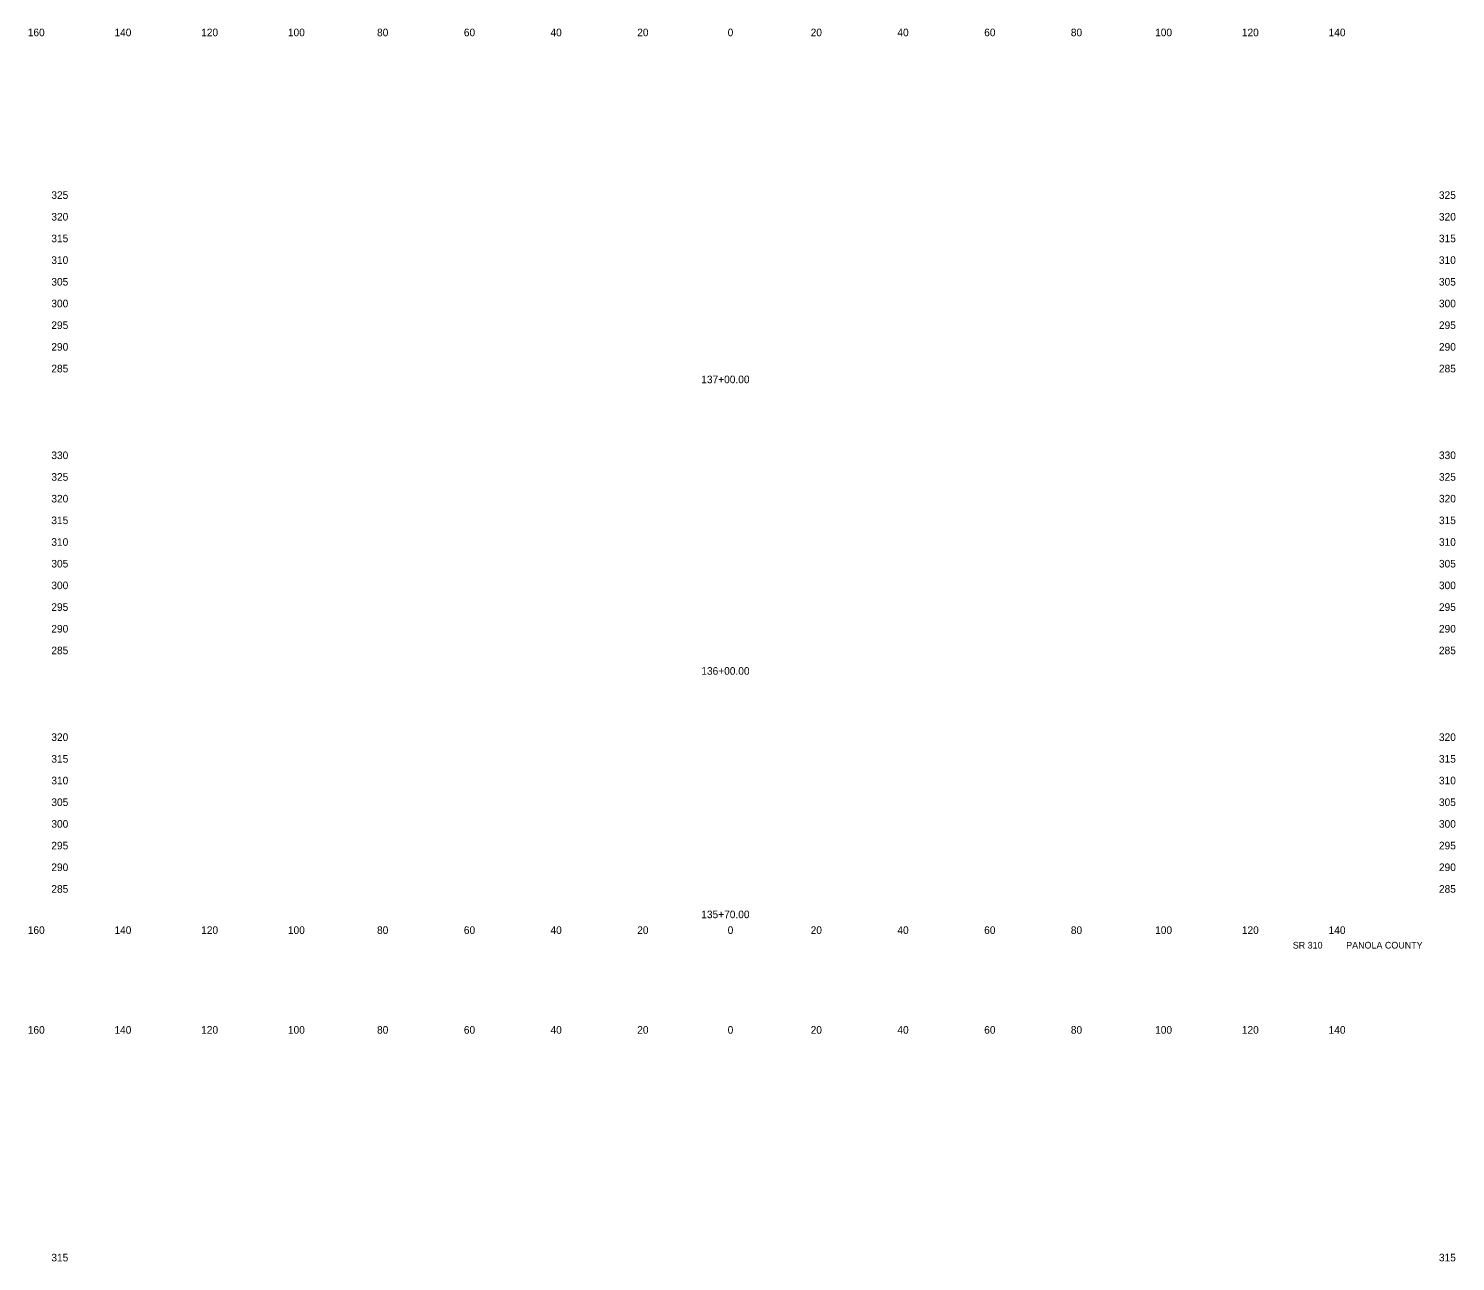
# Model space of a CAD drawing. Extents: x 21481 to 21810, y 6485 to 11067.
# Drawn here: x 21480.9 to 21809.9, y 9632.7 to 9917 of the extents above; entities that cross this region are included whole.
import ezdxf

# ---------------------------------------------------------------- set-up
doc = ezdxf.new("R2010")
doc.units = 0
for name, color, linetype in [('62', 7, 'Continuous'), ('XS_CELL', 7, 'Continuous'), ('XS_P_TX_DCH', 7, 'Continuous'), ('XS_P_TX_FS_BS', 7, 'Continuous')]:
    doc.layers.add(name, color=color, linetype=linetype)

msp = doc.modelspace()

# ---------------------------------------------------------------- texts
at = {"layer": '62'}
for s, p in [('  160  ', (21479.4, 9915.21)), ('  140  ', (21499.39, 9915.21)), ('  120  ', (21519.39, 9915.21)), ('  100  ', (21539.39, 9915.21)), ('  80  ', (21559.95, 9915.21)), ('  60  ', (21579.97, 9915.21)), ('  40  ', (21599.95, 9915.21)), ('  20  ', (21619.95, 9915.21)), ('  0  ', (21640.81, 9915.21)), ('  0  ', (21640.81, 9915.21)), ('  20  ', (21659.95, 9915.21)), ('  40  ', (21679.95, 9915.21)), ('  60  ', (21699.97, 9915.21)), ('  80  ', (21719.95, 9915.21)), ('  100  ', (21739.39, 9915.21)), ('  120  ', (21759.39, 9915.21)), ('  140  ', (21779.39, 9915.21)), ('  160  ', (21479.4, 9708.21)), ('  140  ', (21499.39, 9708.21)), ('  120  ', (21519.39, 9708.21)), ('  100  ', (21539.39, 9708.21)), ('  80  ', (21559.95, 9708.21)), ('  60  ', (21579.97, 9708.21)), ('  40  ', (21599.95, 9708.21)), ('  20  ', (21619.95, 9708.21)), ('  0  ', (21640.81, 9708.21)), ('  0  ', (21640.81, 9708.21)), ('  20  ', (21659.95, 9708.21)), ('  40  ', (21679.95, 9708.21)), ('  60  ', (21699.97, 9708.21)), ('  80  ', (21719.95, 9708.21)), ('  100  ', (21739.39, 9708.21)), ('  120  ', (21759.39, 9708.21)), ('  140  ', (21779.39, 9708.21)), ('  160  ', (21479.4, 9685.21)), ('  140  ', (21499.39, 9685.21)), ('  120  ', (21519.39, 9685.21)), ('  100  ', (21539.39, 9685.21)), ('  80  ', (21559.95, 9685.21)), ('  60  ', (21579.97, 9685.21)), ('  40  ', (21599.95, 9685.21)), ('  20  ', (21619.95, 9685.21)), ('  0  ', (21640.81, 9685.21)), ('  0  ', (21640.81, 9685.21)), ('  20  ', (21659.95, 9685.21)), ('  40  ', (21679.95, 9685.21)), ('  60  ', (21699.97, 9685.21)), ('  80  ', (21719.95, 9685.21)), ('  100  ', (21739.39, 9685.21)), ('  120  ', (21759.39, 9685.21)), ('  140  ', (21779.39, 9685.21))]:
    msp.add_text(s, height=1.75, dxfattribs=at).set_placement(p)
at = {"layer": 'XS_CELL'}
for s, p in [('  325  ', (21484.84, 9877.71)), ('  325  ', (21804.84, 9877.71)), ('  320  ', (21484.84, 9872.71)), ('  320  ', (21804.84, 9872.71)), ('  315  ', (21484.84, 9867.71)), ('  315  ', (21804.84, 9867.71)), ('  310  ', (21484.84, 9862.71)), ('  310  ', (21804.84, 9862.71)), ('  305  ', (21484.84, 9857.71)), ('  305  ', (21804.84, 9857.71)), ('  300  ', (21484.84, 9852.71)), ('  300  ', (21804.84, 9852.71)), ('  295  ', (21484.84, 9847.71)), ('  295  ', (21804.84, 9847.71)), ('  290  ', (21484.84, 9842.71)), ('  290  ', (21804.84, 9842.71)), ('  285  ', (21484.84, 9837.71)), ('  285  ', (21804.84, 9837.71)), ('  330  ', (21484.84, 9817.71)), ('  330  ', (21804.84, 9817.71)), ('  325  ', (21484.84, 9812.71)), ('  325  ', (21804.84, 9812.71)), ('  320  ', (21484.84, 9807.71)), ('  320  ', (21804.84, 9807.71)), ('  315  ', (21484.84, 9802.71)), ('  315  ', (21804.84, 9802.71)), ('  310  ', (21484.84, 9797.71)), ('  310  ', (21804.84, 9797.71)), ('  305  ', (21484.84, 9792.71)), ('  305  ', (21804.84, 9792.71)), ('  300  ', (21484.84, 9787.71)), ('  300  ', (21804.84, 9787.71)), ('  295  ', (21484.84, 9782.71)), ('  295  ', (21804.84, 9782.71)), ('  290  ', (21484.84, 9777.71)), ('  290  ', (21804.84, 9777.71)), ('  285  ', (21484.84, 9772.71)), ('  285  ', (21804.84, 9772.71)), ('  320  ', (21484.84, 9752.71)), ('  320  ', (21804.84, 9752.71)), ('  315  ', (21484.84, 9747.71)), ('  315  ', (21804.84, 9747.71)), ('  310  ', (21484.84, 9742.71)), ('  310  ', (21804.84, 9742.71)), ('  305  ', (21484.84, 9737.71)), ('  305  ', (21804.84, 9737.71)), ('  300  ', (21484.84, 9732.71)), ('  300  ', (21804.84, 9732.71)), ('  295  ', (21484.84, 9727.71)), ('  295  ', (21804.84, 9727.71)), ('  290  ', (21484.84, 9722.71)), ('  290  ', (21804.84, 9722.71)), ('  285  ', (21484.84, 9717.71)), ('  285  ', (21804.84, 9717.71)), ('  315  ', (21484.84, 9632.71)), ('  315  ', (21804.84, 9632.71))]:
    msp.add_text(s, height=1.75, dxfattribs=at).set_placement(p)
at = {"layer": 'XS_P_TX_DCH'}
for s, p in [('  137+00.00  ', (21634.72, 9835.2)), ('  136+00.00  ', (21634.73, 9767.98)), ('  135+70.00  ', (21634.72, 9711.84))]:
    msp.add_text(s, height=1.75, dxfattribs=at).set_placement(p)
at = {"layer": 'XS_P_TX_FS_BS'}
for s, p in [('SR 310', (21772.43, 9704.84)), ('SR 310', (21772.43, 9704.84)), ('SR 310', (21772.43, 9704.84)), ('PANOLA COUNTY', (21784.75, 9704.84)), ('PANOLA COUNTY', (21784.75, 9704.84)), ('PANOLA COUNTY', (21784.75, 9704.84))]:
    msp.add_text(s, height=1.54, dxfattribs=at).set_placement(p)

doc.saveas('drawing.dxf')
